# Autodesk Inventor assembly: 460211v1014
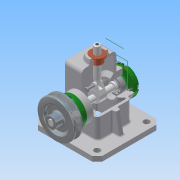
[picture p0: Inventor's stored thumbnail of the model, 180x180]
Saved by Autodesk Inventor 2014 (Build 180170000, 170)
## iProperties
Created: 2016-02
Part Number: 460211v1014
Document SubType Name: Assembly
Designer: User
Author: User
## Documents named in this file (15)
- C:\Documents and Settings\User\My Documents\Inventor\460211V1014\460211v1014.iam
- C:\Documents and Settings\User\My Documents\Inventor\460211V1014\본체.ipt
- C:\Documents and Settings\User\My Documents\Inventor\460211V1014\앞커버.ipt
- C:\Documents and Settings\User\My Documents\Inventor\460211V1014\뒤커버.ipt
- C:\Documents and Settings\User\My Documents\Inventor\460211V1014\편심축.ipt
- C:\Documents and Settings\User\My Documents\Inventor\460211V1014\베어링 12 x 32 x 10.ipt
- C:\Documents and Settings\User\My Documents\Inventor\460211V1014\오일실 12 25 7.ipt
- C:\Documents and Settings\User\My Documents\Inventor\460211V1014\키 4 x 4 x 10.ipt
- C:\Documents and Settings\User\My Documents\Inventor\460211V1014\V벨트풀리.ipt
- C:\Documents and Settings\User\My Documents\Inventor\460211V1014\링크.ipt
- C:\Documents and Settings\User\My Documents\Inventor\460211V1014\슬라이드.ipt
- C:\Documents and Settings\User\My Documents\Inventor\460211V1014\부시.ipt
- C:\Documents and Settings\User\My Documents\Inventor\460211V1014\볼트 M4 x 12.ipt
- C:\Documents and Settings\User\My Documents\Inventor\460211V1014\멈춤나사 M3x8.ipt
- C:\Documents and Settings\User\My Documents\Inventor\460211V1014\핀 5 x 18.ipt
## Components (6 placed, 3 different names)
1. V벨트풀리:1 — 플러쉬:2
2. 핀 5 x 18:1 — 각도:2
3. ISO 4762 M4 x 12:1
4. ISO 4762 M4 x 12:2
5. ISO 4762 M4 x 12:3
6. ISO 4762 M4 x 12:4
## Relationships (2: Flush 1, Angle 1)
- 플러쉬:2 [Flush]: V벨트풀리:1
- 각도:2 [Angle]: 핀 5 x 18:1
